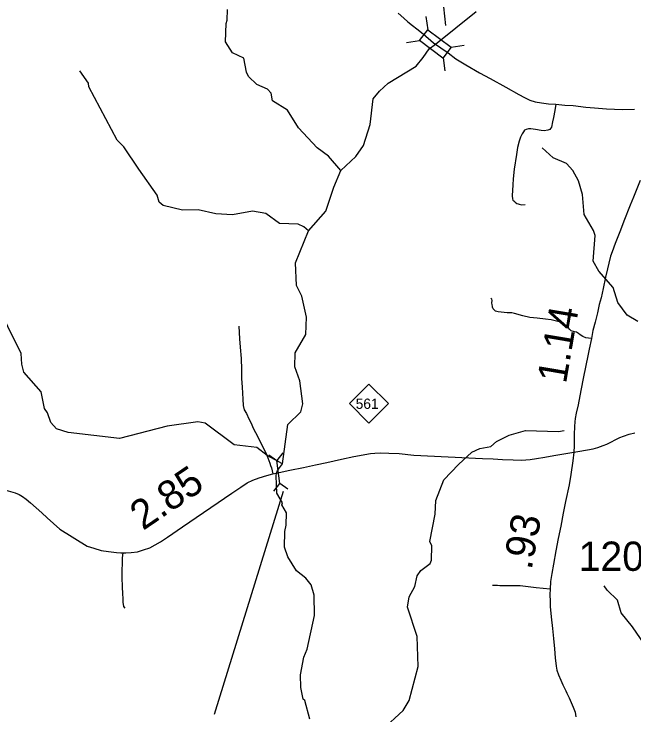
# Model space of a CAD drawing. Extents: x 2290615 to 2522933, y 819489 to 1012715.
# Drawn here: x 2342439 to 2353015, y 916430 to 928394 of the extents above; entities that cross this region are included whole.
import ezdxf

# ---------------------------------------------------------------- set-up
doc = ezdxf.new("R2010")
doc.units = 0
for name, color, linetype in [('Exist Hydrographic Creek Single Shore', 7, 'Continuous'), ('Exist Hydrographic Misc Water Feature', 7, 'Continuous'), ('Exist Road Non-System Type 51', 7, 'Continuous'), ('Exist Road Primary NC Attributed', 7, 'Continuous'), ('Exist Road Primary NC Mileage Hundredths English Label', 7, 'Continuous'), ('Exist Road Primary NC Shield CELL', 7, 'Continuous'), ('Exist Road Primary NC Shield Number Label', 7, 'Continuous'), ('Exist Road Primary NC Structure Culvert CELL', 7, 'Continuous'), ('Exist Road Primary NC Structure Culvert Number Label', 7, 'Continuous'), ('Exist Road Secondary Mileage Hundredths English Label', 7, 'Continuous'), ('Exist Road Secondary Structure Standard Bridge CELL', 7, 'Continuous'), ('Exist Road Secondary Structure Standard Bridge Number Label', 7, 'Continuous'), ('Exist Road Secondary Type 51 Attributed', 7, 'Continuous'), ('Exist Road Secondary Type 51 Number Label', 7, 'Continuous')]:
    doc.layers.add(name, color=color, linetype=linetype)

msp = doc.modelspace()

# ---------------------------------------------------------------- linework, layer by layer
at = {"layer": 'Exist Hydrographic Creek Single Shore'}
for points in [[(2348015, 925721), (2348270, 925965), (2348401, 926151), (2348514, 926510), (2348567, 926945), (2348673, 927078), (2348822, 927215), (2349301, 927504), (2349416, 927653), (2349521, 927800), (2349627, 927881), (2350323, 928439)], [(2353078, 923149), (2352901, 923257), (2352741, 923470), (2352662, 923729), (2352418, 924008), (2352316, 924175), (2352352, 924616), (2352326, 924697), (2352164, 924973), (2352135, 925313), (2352066, 925546), (2351972, 925726), (2351862, 925843), (2351636, 925939), (2351451, 926112)], [(2347461, 924691), (2347757, 925028), (2347893, 925437), (2348015, 925721)], [(2347017, 920719), (2347109, 921387), (2347331, 921607), (2347363, 921739), (2347317, 922131), (2347230, 922371), (2347236, 922614), (2347415, 922923), (2347428, 923222), (2347349, 923580), (2347255, 923763), (2347242, 924147), (2347461, 924691)], [(2347485, 916361), (2347398, 916676), (2347373, 916701), (2347329, 916899), (2347326, 917116), (2347381, 917417), (2347438, 917551), (2347564, 918127), (2347560, 918478), (2347508, 918650), (2347415, 918767), (2347255, 918889), (2347111, 919129), (2347051, 919294), (2347056, 919560), (2347079, 919669), (2347085, 919880), (2347009, 920018), (2347016, 920054), (2346923, 920218), (2346911, 920512), (2346917, 920560), (2346934, 920602), (2347017, 920719)]]:
    msp.add_lwpolyline(points, dxfattribs=at)
at = {"layer": 'Exist Hydrographic Misc Water Feature'}
for points in [[(2348015, 925721), (2347804, 925969), (2347610, 926109), (2347290, 926453), (2347103, 926751), (2346851, 926914), (2346824, 927041), (2346765, 927114), (2346581, 927189), (2346438, 927327), (2346403, 927401), (2346359, 927643), (2346166, 927733), (2346047, 927922), (2346060, 928231), (2346076, 928291), (2346082, 928471)], [(2347461, 924691), (2347385, 924763), (2347284, 924805), (2346968, 924818), (2346732, 924989), (2346507, 925029), (2346166, 924966), (2345883, 924981), (2345582, 925050), (2345315, 925049), (2344981, 925127), (2344914, 925184), (2344879, 925300), (2344566, 925747), (2344311, 926127), (2344201, 926241), (2343716, 927153), (2343707, 927212), (2343562, 927426)], [(2347017, 920719), (2346757, 920858), (2346580, 920998), (2346197, 921041), (2345701, 921412), (2345575, 921436), (2345051, 921362), (2344237, 921151), (2343362, 921250), (2343161, 921314), (2343068, 921422), (2343008, 921587), (2342957, 921663), (2342903, 921943), (2342608, 922283), (2342573, 922416), (2342562, 922599), (2342101, 923519)], [(2348721, 916175), (2349075, 916505), (2349181, 916680), (2349333, 917257), (2349318, 917772), (2349154, 918271), (2349177, 918446), (2349275, 918621), (2349314, 918806), (2349380, 918897), (2349537, 919015), (2349561, 919075), (2349566, 919315), (2349532, 919393), (2349626, 919859), (2349632, 920093), (2349769, 920443), (2350024, 920706), (2350247, 920915), (2350388, 920977), (2350571, 921011), (2350670, 921097), (2350885, 921208), (2351167, 921285), (2351726, 921268), (2351825, 921286)], [(2354226, 912098), (2354233, 912113), (2354470, 912610), (2354493, 912828), (2354390, 913043), (2354152, 913408), (2353925, 913628), (2353728, 914044), (2353601, 914199), (2353426, 914264), (2353367, 914331), (2353323, 914523), (2353325, 915012), (2353417, 915656), (2353481, 915872), (2353511, 916182), (2353358, 916405), (2353312, 917463), (2352990, 917933), (2352796, 918171), (2352735, 918388), (2352558, 918562), (2352507, 918635)]]:
    msp.add_lwpolyline(points, dxfattribs=at)
at = {"layer": 'Exist Road Non-System Type 51'}
for points in [[(2351684, 926856), (2351665, 926747), (2351642, 926630), (2351626, 926555), (2351607, 926465), (2351592, 926440), (2351578, 926423), (2351546, 926411), (2351480, 926402), (2351429, 926407), (2351336, 926421), (2351258, 926436), (2351217, 926436), (2351177, 926426), (2351150, 926410), (2351131, 926385), (2351108, 926347), (2351081, 926293), (2351056, 926226), (2351029, 926117), (2351008, 925998), (2350971, 925744), (2350956, 925584), (2350948, 925478), (2350939, 925293), (2350943, 925237), (2350951, 925218), (2350966, 925205), (2350989, 925184), (2351019, 925163), (2351041, 925156), (2351058, 925149), (2351095, 925138), (2351158, 925145)], [(2352290, 922854), (2352240, 922859), (2352191, 922870), (2352141, 922893), (2352098, 922919), (2352069, 922940), (2352034, 922963), (2351999, 922969), (2351946, 922987), (2351920, 923010), (2351890, 923041), (2351849, 923077), (2351804, 923111), (2351764, 923133), (2351670, 923159), (2351603, 923174), (2351503, 923188), (2351363, 923201), (2351239, 923217), (2351121, 923244), (2350975, 923284), (2350930, 923295), (2350849, 923293), (2350699, 923309), (2350650, 923321), (2350639, 923332), (2350615, 923361), (2350603, 923388), (2350599, 923409), (2350595, 923430), (2350592, 923467), (2350593, 923502), (2350588, 923526), (2350574, 923547)], [(2346274, 923067), (2346287, 922848), (2346295, 922710), (2346311, 922513), (2346317, 922326), (2346322, 922172), (2346333, 922023), (2346343, 921820), (2346349, 921714), (2346367, 921639), (2346402, 921575), (2346447, 921487), (2346479, 921421), (2346525, 921314), (2346590, 921191), (2346654, 921059), (2346723, 920930), (2346746, 920875), (2346769, 920819), (2346801, 920731), (2346814, 920691), (2346833, 920651), (2346854, 920544)], [(2344296, 919199), (2344290, 919160), (2344283, 919104), (2344284, 919067), (2344281, 919008), (2344278, 918907), (2344276, 918785), (2344278, 918723), (2344286, 918670), (2344286, 918582), (2344289, 918531), (2344292, 918491), (2344294, 918425), (2344297, 918353), (2344305, 918281), (2344329, 918252)], [(2351583, 918578), (2351346, 918599), (2351073, 918633), (2350842, 918636), (2350728, 918636), (2350686, 918638), (2350603, 918640)]]:
    msp.add_lwpolyline(points, dxfattribs=at)
at = {"layer": 'Exist Road Primary NC Attributed'}
for points in [[(2351989, 920916), (2352058, 920929), (2352220, 920956), (2352317, 920975), (2352396, 920995), (2352489, 921030), (2352551, 921055), (2352634, 921094), (2352696, 921126), (2352776, 921169), (2352837, 921190), (2352935, 921222), (2353028, 921244)], [(2342300, 920267), (2342461, 920221), (2342529, 920192), (2342584, 920161), (2342644, 920116), (2342717, 920050), (2342814, 919968), (2342913, 919879), (2343006, 919794), (2343218, 919602), (2343684, 919312), (2343798, 919275), (2343928, 919237), (2344051, 919219), (2344189, 919202), (2344260, 919198), (2344325, 919198), (2344345, 919200), (2344437, 919201), (2344546, 919215), (2344650, 919248), (2344754, 919285), (2344849, 919332), (2344940, 919385), (2345059, 919465), (2345315, 919644), (2346152, 920214), (2346307, 920317), (2346418, 920395), (2346513, 920436), (2346619, 920479), (2346754, 920517), (2346854, 920544), (2346960, 920569), (2347143, 920608), (2347375, 920654), (2347580, 920699), (2347775, 920741), (2348025, 920796), (2348234, 920842), (2348519, 920894), (2348595, 920901), (2348697, 920904), (2348835, 920898), (2349011, 920892), (2349258, 920867), (2350428, 920807), (2350610, 920801), (2350770, 920793), (2350953, 920785), (2351098, 920780), (2351244, 920792), (2351353, 920809), (2351495, 920829), (2351649, 920858), (2351818, 920885), (2351989, 920916)]]:
    msp.add_lwpolyline(points, dxfattribs=at)
at = {"layer": 'Exist Road Primary NC Shield CELL'}
msp.add_lwpolyline([(2348159, 921745), (2348492, 922078), (2348825, 921745), (2348492, 921412)], close=True, dxfattribs=at)
at = {"layer": 'Exist Road Primary NC Structure Culvert CELL'}
for p, q in [((2346787, 920873), (2346922, 920776)), ((2347026, 920905), (2346922, 920776)), ((2346974, 920383), (2346922, 920776)), ((2346870, 920253), (2346974, 920383)), ((2347109, 920285), (2346974, 920383))]:
    msp.add_line(p, q, dxfattribs=at)
at = {"layer": 'Exist Road Primary NC Structure Culvert Number Label'}
msp.add_line((2347028, 920244), (2345855, 916438), dxfattribs=at)
at = {"layer": 'Exist Road Secondary Structure Standard Bridge CELL'}
for p, q in [((2349465, 928350), (2349497, 928126)), ((2349134, 927908), (2349358, 927940)), ((2349894, 927828), (2350118, 927861)), ((2349758, 927647), (2349791, 927423))]:
    msp.add_line(p, q, dxfattribs=at)
msp.add_lwpolyline([(2349497, 928126), (2349894, 927829), (2349756, 927643), (2349358, 927940)], close=True, dxfattribs=at)
at = {"layer": 'Exist Road Secondary Structure Standard Bridge Number Label'}
msp.add_line((2349807, 928201), (2349103, 934350), dxfattribs=at)
at = {"layer": 'Exist Road Secondary Type 51 Attributed'}
for points in [[(2348994, 928407), (2349088, 928322), (2349159, 928260), (2349234, 928200), (2349309, 928142), (2349420, 928056), (2349597, 927905)], [(2349597, 927905), (2349845, 927731), (2349977, 927632), (2350147, 927526), (2350377, 927393), (2350563, 927296), (2350828, 927147), (2351050, 927022), (2351148, 926967), (2351238, 926924), (2351329, 926894), (2351438, 926876), (2351555, 926860), (2351684, 926856), (2351835, 926839), (2351979, 926831), (2352191, 926807), (2352340, 926794), (2352544, 926775), (2352684, 926771), (2352824, 926767), (2353024, 926771)], [(2353122, 925550), (2353007, 925270), (2352951, 925133), (2352842, 924859), (2352783, 924704), (2352693, 924479), (2352641, 924334), (2352617, 924259), (2352586, 924142), (2352563, 924047), (2352531, 923905), (2352489, 923708), (2352453, 923549), (2352420, 923434), (2352390, 923296), (2352350, 923135), (2352313, 922993), (2352290, 922854), (2352251, 922673), (2352227, 922561), (2352153, 922199), (2352107, 921970), (2352063, 921723), (2352031, 921584), (2352014, 921489), (2352007, 921432), (2352000, 921353), (2351995, 921216), (2351992, 921126), (2351994, 921024), (2351989, 920916)], [(2351989, 920916), (2351972, 920768), (2351940, 920535), (2351907, 920356), (2351849, 920073), (2351805, 919874), (2351766, 919655), (2351722, 919445), (2351683, 919232), (2351643, 919005), (2351612, 918846), (2351591, 918709), (2351583, 918578), (2351581, 918485), (2351584, 918365), (2351586, 918279), (2351604, 918106), (2351625, 917906), (2351641, 917734), (2351659, 917561), (2351673, 917405), (2351690, 917266), (2351701, 917198), (2351726, 917117), (2351766, 917025), (2351800, 916947), (2351850, 916845), (2351872, 916802), (2351910, 916725), (2351946, 916646), (2351977, 916565), (2352009, 916480), (2352025, 916398)]]:
    msp.add_lwpolyline(points, dxfattribs=at)

# ---------------------------------------------------------------- texts
at = {"layer": 'Exist Road Primary NC Mileage Hundredths English Label'}
msp.add_text('2.85', height=500, rotation=34.2469, dxfattribs=at).set_placement((2344639, 919570))
at = {"layer": 'Exist Road Primary NC Shield Number Label'}
msp.add_text('561', height=175, dxfattribs=at).set_placement((2348268, 921655))
at = {"layer": 'Exist Road Secondary Mileage Hundredths English Label'}
for s, rotation, p in [('1.14', 80.4044, (2351855, 922073)), ('.93', 79.5786, (2351267, 918895))]:
    msp.add_text(s, height=500, rotation=rotation, dxfattribs=at).set_placement(p)
at = {"layer": 'Exist Road Secondary Type 51 Number Label'}
msp.add_text('1200', height=500, rotation=360, dxfattribs=at).set_placement((2352071, 918890))

doc.saveas('drawing.dxf')
